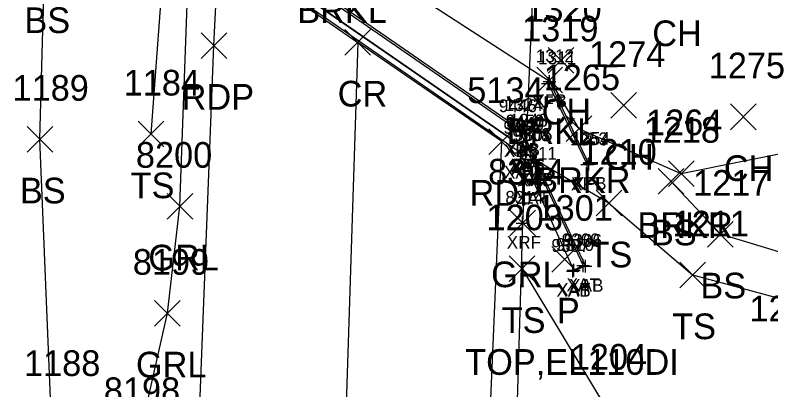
# Model space of a CAD drawing. Extents: x 1482574 to 1485769, y 580696 to 595649.
# Drawn here: x 1485137.8 to 1485196.7, y 581446.4 to 581475.6 of the extents above; entities that cross this region are included whole.
import ezdxf

# ---------------------------------------------------------------- set-up
doc = ezdxf.new("R2010")
doc.units = 0
for name, color, linetype in [('B_A', 7, 'Continuous'), ('B_I', 7, 'Continuous'), ('B_TIC', 7, 'Continuous'), ('BFT', 7, 'Continuous'), ('BR', 7, 'Continuous'), ('BSE', 7, 'Continuous'), ('BSUBM', 7, 'Continuous'), ('D_A', 7, 'Continuous'), ('D_C', 7, 'Continuous'), ('D_I', 7, 'Continuous'), ('D_TIC', 7, 'Continuous'), ('L_A', 7, 'Continuous'), ('L_I', 7, 'Continuous'), ('L_TIC', 7, 'Continuous'), ('LAWE', 7, 'Continuous'), ('LELB', 7, 'Continuous'), ('P_A', 7, 'Continuous'), ('P_I', 7, 'Continuous'), ('P_TIC', 7, 'Continuous'), ('PET', 7, 'Continuous'), ('PRC', 7, 'Continuous'), ('R_A', 7, 'Continuous'), ('R_I', 7, 'Continuous'), ('R_TIC', 7, 'Continuous'), ('RGR', 7, 'Continuous')]:
    doc.layers.add(name, color=color, linetype=linetype)

msp = doc.modelspace()

# ---------------------------------------------------------------- linework, layer by layer
at = {"layer": 'B_TIC'}
for p, q in [((1485179.378, 581470.225), (1485179.454, 581470.225)), ((1485179.487, 581470.386), (1485179.563, 581470.386)), ((1485177.348, 581466.586), (1485177.424, 581466.586)), ((1485177.197, 581466.495), (1485177.273, 581466.495)), ((1485177.243, 581464.818), (1485177.319, 581464.818)), ((1485177.708, 581465.113), (1485177.784, 581465.113)), ((1485177.731, 581465.369), (1485177.807, 581465.369)), ((1485177.738, 581465.054), (1485177.814, 581465.054)), ((1485177.758, 581465.304), (1485177.834, 581465.304)), ((1485178.266, 581464.227), (1485178.342, 581464.227)), ((1485178.414, 581464.254), (1485178.49, 581464.254)), ((1485182.426, 581463.919), (1485182.502, 581463.919)), ((1485182.571, 581463.955), (1485182.647, 581463.955)), ((1485178.165, 581462.787), (1485178.241, 581462.787)), ((1485177.4, 581459.359), (1485177.476, 581459.359)), ((1485182.118, 581456.042), (1485182.194, 581456.042)), ((1485182.302, 581456.002), (1485182.378, 581456.002)), ((1485181.308, 581455.612), (1485181.384, 581455.612)), ((1485181.38, 581455.687), (1485181.456, 581455.687))]:
    msp.add_line(p, q, dxfattribs=at)
for points in [[(1485179.375, 581469.725), (1485179.375, 581470.725)], [(1485179.484, 581469.886), (1485179.484, 581470.886)], [(1485178.875, 581470.225), (1485179.875, 581470.225)], [(1485178.984, 581470.386), (1485179.984, 581470.386)], [(1485176.845, 581466.586), (1485177.845, 581466.586)], [(1485177.194, 581465.995), (1485177.194, 581466.995)], [(1485177.345, 581466.086), (1485177.345, 581467.086)], [(1485176.694, 581466.495), (1485177.694, 581466.495)], [(1485177.705, 581464.613), (1485177.705, 581465.613)], [(1485177.728, 581464.869), (1485177.728, 581465.869)], [(1485177.735, 581464.554), (1485177.735, 581465.554)], [(1485177.755, 581464.804), (1485177.755, 581465.804)], [(1485176.74, 581464.818), (1485177.74, 581464.818)], [(1485177.205, 581465.113), (1485178.205, 581465.113)], [(1485177.228, 581465.369), (1485178.228, 581465.369)], [(1485177.235, 581465.054), (1485178.235, 581465.054)], [(1485177.24, 581464.318), (1485177.24, 581465.318)], [(1485177.255, 581465.304), (1485178.255, 581465.304)], [(1485177.763, 581464.227), (1485178.763, 581464.227)], [(1485177.911, 581464.254), (1485178.911, 581464.254)], [(1485178.263, 581463.727), (1485178.263, 581464.727)], [(1485178.411, 581463.754), (1485178.411, 581464.754)], [(1485182.423, 581463.419), (1485182.423, 581464.419)], [(1485182.568, 581463.455), (1485182.568, 581464.455)], [(1485181.923, 581463.919), (1485182.923, 581463.919)], [(1485182.068, 581463.955), (1485183.068, 581463.955)], [(1485178.162, 581462.287), (1485178.162, 581463.287)], [(1485177.662, 581462.787), (1485178.662, 581462.787)], [(1485177.397, 581458.859), (1485177.397, 581459.859)], [(1485176.897, 581459.359), (1485177.897, 581459.359)], [(1485181.305, 581455.112), (1485181.305, 581456.112)], [(1485181.377, 581455.187), (1485181.377, 581456.187)], [(1485181.615, 581456.042), (1485182.615, 581456.042)], [(1485181.799, 581456.002), (1485182.799, 581456.002)], [(1485182.115, 581455.542), (1485182.115, 581456.542)], [(1485182.299, 581455.502), (1485182.299, 581456.502)], [(1485180.805, 581455.612), (1485181.805, 581455.612)], [(1485180.877, 581455.687), (1485181.877, 581455.687)]]:
    msp.add_lwpolyline(points, dxfattribs=at)
at = {"layer": 'BFT'}
for points in [[(1485179.484, 581470.386), (1485163.91, 581480.484), (1485163.319, 581479.815), (1485152.276, 581487.344)], [(1485179.375, 581470.225), (1485182.423, 581463.919)], [(1485179.484, 581470.386), (1485182.568, 581463.955)]]:
    msp.add_lwpolyline(points, dxfattribs=at)
at = {"layer": 'BR'}
msp.add_lwpolyline([(1485179.497, 581503.607), (1485178.401, 581482.357), (1485177.397, 581459.359)], dxfattribs=at)
at = {"layer": 'BSE'}
for points in [[(1485150.727, 581483.768), (1485177.705, 581465.113)], [(1485150.737, 581483.991), (1485151.987, 581483.922), (1485177.194, 581466.495)], [(1485177.194, 581466.495), (1485177.728, 581465.369)], [(1485177.705, 581465.113), (1485177.728, 581465.369)]]:
    msp.add_lwpolyline(points, dxfattribs=at)
at = {"layer": 'BSUBM'}
for points in [[(1485150.698, 581483.745), (1485177.735, 581465.054), (1485177.755, 581465.304)], [(1485152.007, 581484.099), (1485177.345, 581466.586)], [(1485177.24, 581464.818), (1485150.688, 581483.178)], [(1485177.345, 581466.586), (1485178.411, 581464.254)], [(1485178.162, 581462.787), (1485177.24, 581464.818)], [(1485177.755, 581465.304), (1485177.728, 581465.369)], [(1485178.263, 581464.227), (1485177.755, 581465.304)], [(1485178.263, 581464.227), (1485182.115, 581456.042), (1485181.377, 581455.687), (1485178.162, 581462.787)], [(1485178.411, 581464.254), (1485182.299, 581456.002), (1485181.305, 581455.612)]]:
    msp.add_lwpolyline(points, dxfattribs=at)
at = {"layer": 'D_TIC'}
for points in [[(1485179.684, 581455.531), (1485181.684, 581457.531)], [(1485181.684, 581455.531), (1485179.684, 581457.531)]]:
    msp.add_lwpolyline(points, dxfattribs=at)
at = {"layer": 'L_TIC'}
for points in [[(1485179.386, 581471.039), (1485181.386, 581473.039)], [(1485181.386, 581471.039), (1485179.386, 581473.039)], [(1485178.494, 581469.507), (1485180.494, 581471.507)], [(1485180.494, 581469.507), (1485178.494, 581471.507)], [(1485184.265, 581467.519), (1485186.265, 581469.519)], [(1485186.265, 581467.519), (1485184.265, 581469.519)], [(1485193.592, 581466.633), (1485195.592, 581468.633)], [(1485195.592, 581466.633), (1485193.592, 581468.633)], [(1485147.431, 581465.294), (1485149.431, 581467.294)], [(1485149.431, 581465.294), (1485147.431, 581467.294)], [(1485180.78, 581465.701), (1485182.78, 581467.701)], [(1485182.78, 581465.701), (1485180.78, 581467.701)], [(1485138.772, 581464.888), (1485140.772, 581466.888)], [(1485140.772, 581464.888), (1485138.772, 581466.888)], [(1485188.753, 581462.204), (1485190.753, 581464.204)], [(1485190.753, 581462.204), (1485188.753, 581464.204)], [(1485187.955, 581461.62), (1485189.955, 581463.62)], [(1485189.955, 581461.62), (1485187.955, 581463.62)], [(1485183.116, 581459.907), (1485185.116, 581461.907)], [(1485185.116, 581459.907), (1485183.116, 581461.907)], [(1485191.807, 581457.486), (1485193.807, 581459.486)], [(1485193.807, 581457.486), (1485191.807, 581459.486)], [(1485176.354, 581454.796), (1485178.354, 581456.796)], [(1485178.354, 581454.796), (1485176.354, 581456.796)], [(1485189.639, 581454.31), (1485191.639, 581456.31)], [(1485191.639, 581454.31), (1485189.639, 581456.31)]]:
    msp.add_lwpolyline(points, dxfattribs=at)
at = {"layer": 'LAWE'}
for points in [[(1485179.494, 581470.507), (1485181.78, 581466.701)], [(1485231.409, 581442.649), (1485219.848, 581464.802), (1485199.953, 581465.231), (1485189.753, 581463.204), (1485181.78, 581466.701)]]:
    msp.add_lwpolyline(points, dxfattribs=at)
at = {"layer": 'LELB'}
for points in [[(1485149.54, 581481.38), (1485148.431, 581466.294)], [(1485142.007, 581414.572), (1485140.662, 581444.441), (1485139.772, 581465.888), (1485140.124, 581479.162)], [(1485184.116, 581460.907), (1485178.411, 581464.254)], [(1485225.904, 581447.987), (1485217.755, 581453.972), (1485201.209, 581455.953), (1485192.807, 581458.486), (1485188.955, 581462.62)], [(1485184.116, 581460.907), (1485190.639, 581455.31), (1485203.798, 581451.76), (1485219.73, 581447.915)], [(1485177.354, 581455.796), (1485183.919, 581444.933), (1485192.167, 581437.394), (1485202.236, 581424.349)]]:
    msp.add_lwpolyline(points, dxfattribs=at)
at = {"layer": 'P_TIC'}
for points in [[(1485163.546, 581472.437), (1485165.546, 581474.437)], [(1485165.546, 581472.437), (1485163.546, 581474.437)], [(1485152.332, 581472.187), (1485154.332, 581474.187)], [(1485154.332, 581472.187), (1485152.332, 581474.187)], [(1485174.773, 581464.71), (1485176.773, 581466.71)], [(1485176.773, 581464.71), (1485174.773, 581466.71)]]:
    msp.add_lwpolyline(points, dxfattribs=at)
at = {"layer": 'PET'}
for points in [[(1485153.332, 581473.187), (1485153.706, 581480.937)], [(1485153.706, 581480.937), (1485164.546, 581473.437)], [(1485151.944, 581437.846), (1485153.332, 581473.187)], [(1485175.773, 581465.71), (1485164.546, 581473.437)], [(1485174.53, 581436.527), (1485175.773, 581465.71)]]:
    msp.add_lwpolyline(points, dxfattribs=at)
at = {"layer": 'PRC'}
msp.add_lwpolyline([(1485164.546, 581473.437), (1485163.372, 581437.164)], dxfattribs=at)
at = {"layer": 'R_TIC'}
for points in [[(1485149.681, 581459.668), (1485151.681, 581461.668)], [(1485151.681, 581459.668), (1485149.681, 581461.668)], [(1485176.397, 581458.359), (1485178.397, 581460.359)], [(1485178.397, 581458.359), (1485176.397, 581460.359)], [(1485148.717, 581451.328), (1485150.717, 581453.328)], [(1485150.717, 581451.328), (1485148.717, 581453.328)]]:
    msp.add_lwpolyline(points, dxfattribs=at)
at = {"layer": 'RGR'}
for points in [[(1485144.034, 581434.999), (1485147.446, 581442.328), (1485149.717, 581452.328), (1485150.681, 581460.668), (1485151.459, 581482.124)], [(1485177.397, 581459.359), (1485176.475, 581429.08), (1485177.21, 581413.762), (1485180.353, 581402.564)]]:
    msp.add_lwpolyline(points, dxfattribs=at)

# ---------------------------------------------------------------- texts
at = {"layer": 'B_A'}
for s, p in [('XFT', (1485178.119, 581468.225)), ('XFB', (1485178.244, 581468.386)), ('XBS', (1485175.934, 581464.495)), ('XAB', (1485176.065, 581464.586)), ('XAT', (1485176.46, 581463.304)), ('XBS', (1485176.468, 581463.369)), ('XAT', (1485175.945, 581462.818)), ('XAT', (1485176.44, 581463.054)), ('XBS', (1485176.445, 581463.113)), ('XAT', (1485176.968, 581462.227)), ('XAB', (1485177.131, 581462.254)), ('XFT', (1485181.167, 581461.919)), ('XFB', (1485181.328, 581461.955)), ('XAT', (1485176.867, 581460.787)), ('XRF', (1485176.157, 581457.359)), ('XAT', (1485180.82, 581454.042)), ('XAB', (1485181.019, 581454.002)), ('XAB', (1485180.025, 581453.612)), ('XAT', (1485180.082, 581453.687))]:
    msp.add_text(s, height=1, dxfattribs=at).set_placement(p)
at = {"layer": 'B_I'}
for s, p in [('1312', (1485178.421, 581471.886)), ('1311', (1485178.595, 581471.725)), ('9446', (1485175.537, 581467.995)), ('1324', (1485175.999, 581468.086)), ('9450', (1485176.082, 581466.804)), ('1248', (1485176.382, 581466.869)), ('9451', (1485175.894, 581466.318)), ('9447', (1485176.075, 581466.613)), ('9449', (1485176.101, 581466.554)), ('9308', (1485176.594, 581465.727)), ('9305', (1485176.742, 581465.754)), ('1253', (1485181.077, 581465.419)), ('1254', (1485181.222, 581465.455)), ('9311', (1485177.099, 581464.287)), ('8314', (1485176.051, 581460.859)), ('9309', (1485180.442, 581457.542)), ('9306', (1485180.602, 581457.502)), ('9307', (1485179.636, 581457.112)), ('9310', (1485179.987, 581457.187))]:
    msp.add_text(s, height=1, dxfattribs=at).set_placement(p)
at = {"layer": 'D_A'}
msp.add_text('P', height=2, dxfattribs=at).set_placement((1485180.062, 581451.531))
at = {"layer": 'D_C'}
msp.add_text('TOP,EL110DI', height=2, dxfattribs=at).set_placement((1485172.92, 581447.531))
at = {"layer": 'D_I'}
msp.add_text('1301', height=2, dxfattribs=at).set_placement((1485178.479, 581459.531))
at = {"layer": 'L_A'}
for s, p in [('BRKL', (1485159.834, 581474.946)), ('BS', (1485138.565, 581474.162)), ('CH', (1485187.499, 581473.142)), ('CH', (1485178.874, 581467.039)), ('BRKL', (1485176.14, 581465.507)), ('CH', (1485183.753, 581463.519)), ('CH', (1485193.08, 581462.633)), ('BRKR', (1485178.371, 581461.701)), ('TS', (1485146.84, 581461.294)), ('BS', (1485138.213, 581460.888)), ('BRKR', (1485186.344, 581458.204)), ('BS', (1485187.396, 581457.62)), ('TS', (1485182.525, 581455.907)), ('BS', (1485191.248, 581453.486)), ('TS', (1485175.763, 581450.796)), ('TS', (1485189.048, 581450.31))]:
    msp.add_text(s, height=2, dxfattribs=at).set_placement(p)
at = {"layer": 'L_I'}
for s, p in [('1320', (1485177.606, 581475.039)), ('1319', (1485177.36, 581473.507)), ('1274', (1485182.572, 581471.519)), ('1275', (1485191.899, 581470.633)), ('1184', (1485146.305, 581469.294)), ('1265', (1485179.04, 581469.701)), ('1189', (1485137.638, 581468.888)), ('1264', (1485187.013, 581466.204)), ('1218', (1485186.829, 581465.62)), ('1210', (1485181.903, 581463.907)), ('1217', (1485190.681, 581461.486)), ('1203', (1485174.582, 581458.796)), ('1211', (1485189.08, 581458.31)), ('1209', (1485195.073, 581451.693)), ('1204', (1485181.147, 581447.933)), ('1188', (1485138.536, 581447.441))]:
    msp.add_text(s, height=2, dxfattribs=at).set_placement(p)
at = {"layer": 'P_A'}
for s, p in [('RDP', (1485150.82, 581468.187)), ('CR', (1485162.979, 581468.437)), ('RDP', (1485173.261, 581460.71))]:
    msp.add_text(s, height=2, dxfattribs=at).set_placement(p)
at = {"layer": 'P_I'}
msp.add_text('5134', height=2, dxfattribs=at).set_placement((1485173.08, 581468.71))
at = {"layer": 'R_A'}
for p in [(1485148.224, 581455.668), (1485174.94, 581454.359), (1485147.26, 581447.328)]:
    msp.add_text('GRL', height=2, dxfattribs=at).set_placement(p)
at = {"layer": 'R_I'}
for s, p in [('8200', (1485147.256, 581463.668)), ('8314', (1485174.704, 581462.359)), ('8199', (1485147.016, 581455.328)), ('8198', (1485144.753, 581445.328))]:
    msp.add_text(s, height=2, dxfattribs=at).set_placement(p)

doc.saveas('drawing.dxf')
